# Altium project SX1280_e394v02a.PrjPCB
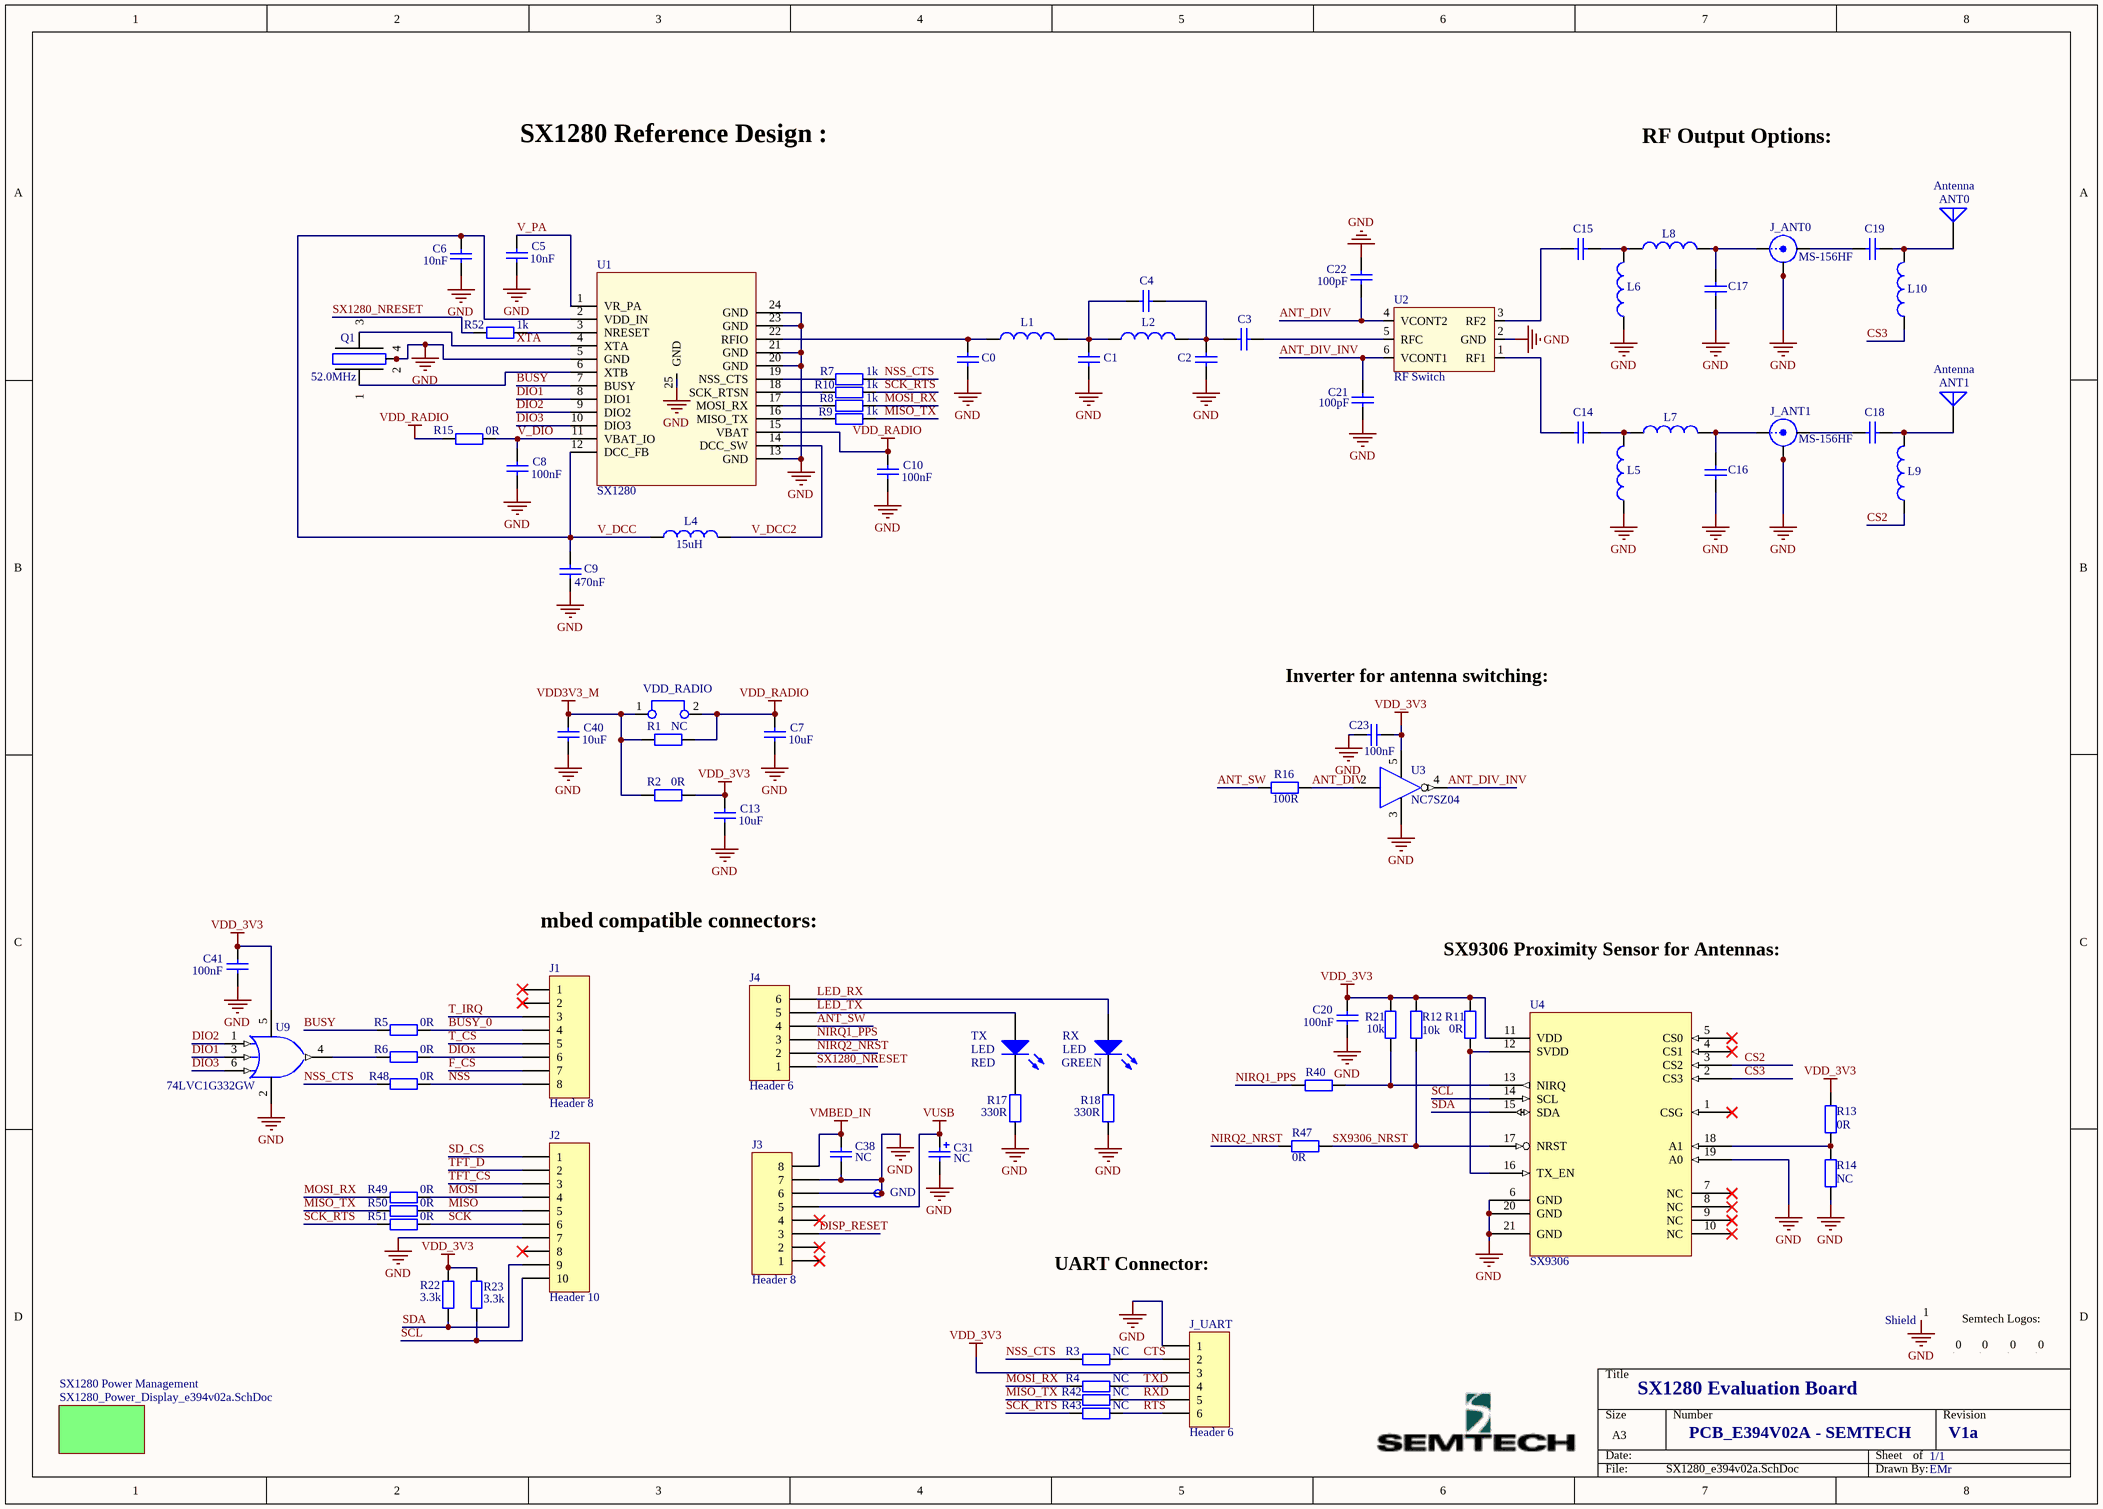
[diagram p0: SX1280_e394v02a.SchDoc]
2 sheets, 155 parts. Net scope: global (net labels, ports and power ports of the same name join across sheets).
Board file: SX1280_e394v02a.PcbDoc
Sheets:
  SX1280_e394v02a.SchDoc
    SX1280 Power Management = SX1280_Power_Display_e394v02a.SchDoc

## Sheet SX1280_e394v02a.SchDoc
size A3; DocumentNumber: 1; SheetNumber: 1; SheetTotal: 2; VersionControl_RevNumber: 1

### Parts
ANT0  Antenna  [ANT_2.4GHz_microstrip]
ANT1  Antenna  [ANT_2.4GHz_microstrip]
C0  Cap  [rlc_402_smd]  (value not drawn)
C1  Cap  [rlc_402_smd]  (value not drawn)
C2  Cap  [rlc_402_smd]  (value not drawn)
C3  Cap  [rlc_402_smd]  (value not drawn)
C4  Cap  [rlc_402_smd]  (value not drawn)
C5  value 10nF  [rlc_402_smd]  (hidden comment: Cap)
C6  value 10nF  [rlc_402_smd]  (hidden comment: Cap)
C7  value 10uF  [rlc_805_smd]  (hidden comment: Cap)
C8  value 100nF  [rlc_402_smd]  (hidden comment: Cap)
C9  value 470nF  [rlc_402_smd]  (hidden comment: Cap)
C10  value 100nF  [rlc_402_smd]  (hidden comment: Cap)
C13  value 10uF  [rlc_805_smd]  (hidden comment: Cap)
C14  Cap  [rlc_402_smd]  (value not drawn)
C15  Cap  [rlc_402_smd]  (value not drawn)
C16  Cap  [rlc_402_smd]  (value not drawn)
C17  Cap  [rlc_402_smd]  (value not drawn)
C18  Cap  [rlc_402_smd]  (value not drawn)
C19  Cap  [rlc_402_smd]  (value not drawn)
C20  value 100nF  [rlc_402_smd]  (hidden comment: Cap)
C21  value 100pF  [rlc_402_smd]  (hidden comment: Cap)
C22  value 100pF  [rlc_402_smd]  (hidden comment: Cap)
C23  value 100nF  [rlc_402_smd]  (hidden comment: Cap)
C31  value NC  [CD3216-1206]  (hidden comment: Cap Pol)
C38  value NC  [rlc_805_smd]  (hidden comment: Cap)
C40  value 10uF  [rlc_805_smd]  (hidden comment: Cap)
C41  value 100nF  [rlc_402_smd]  (hidden comment: Cap)
GND  Test Pin  [pin_0.9mm]  (value not drawn)
J1  Header 8  [HDR1X8]
J2  Header 10  [HDR1X10]
J3  Header 8  [HDR1X8]
J4  Header 6  [HDR1X6]
J_ANT0  MS-156HF  [MS-156HF Hirose]
J_ANT1  MS-156HF  [MS-156HF Hirose]
J_UART  Header 6  [HDR1X6]
L1  Inductor  [rlc_402_smd]  (value not drawn)
L2  Inductor  [rlc_402_smd]  (value not drawn)
L4  value 15uH  [rlc_805_smd enlarged]  (hidden comment: Inductor)
L5  Inductor  [rlc_402_smd]  (value not drawn)
L6  Inductor  [rlc_402_smd]  (value not drawn)
L7  Inductor  [rlc_402_smd]  (value not drawn)
L8  Inductor  [rlc_402_smd]  (value not drawn)
L9  Inductor  [rlc_402_smd]  (value not drawn)
L10  Inductor  [rlc_402_smd]  (value not drawn)
Logo_Bot  Logo symbol  [logo_semtech_horiz_size4]  (value not drawn)
Logo_ESD  Logo symbol  [Logo ESD]  (value not drawn)
Logo_Recycling1  Logo symbol  [Logo Recycling1]  (value not drawn)
Logo_Semtech_S  Logo symbol  [logo_semtech_horiz_size3]  (value not drawn)
Q1  value 52.0MHz  [nd2016da]  (hidden comment: Xtal)
R1  value NC  [rlc_603_smd]  (hidden comment: Resistor)
R2  value 0R  [rlc_603_smd]  (hidden comment: Resistor)
R3  value NC  [rlc_402_smd]  (hidden comment: Resistor)
R4  value NC  [rlc_402_smd]  (hidden comment: Resistor)
R5  value 0R  [rlc_402_smd]  (hidden comment: Resistor)
R6  value 0R  [rlc_402_smd]  (hidden comment: Resistor)
R7  value 1k  [rlc_201_smd]  (hidden comment: Resistor)
R8  value 1k  [rlc_201_smd]  (hidden comment: Resistor)
R9  value 1k  [rlc_201_smd]  (hidden comment: Resistor)
R10  value 1k  [rlc_201_smd]  (hidden comment: Resistor)
R11  value 0R  [rlc_402_smd]  (hidden comment: Resistor)
R12  value 10k  [rlc_402_smd]  (hidden comment: Resistor)
R13  value 0R  [rlc_402_smd]  (hidden comment: Resistor)
R14  value NC  [rlc_402_smd]  (hidden comment: Resistor)
R15  value 0R  [rlc_402_smd]  (hidden comment: Resistor)
R16  value 100R  [rlc_402_smd]  (hidden comment: Resistor)
R17  value 330R  [rlc_402_smd]  (hidden comment: Resistor)
R18  value 330R  [rlc_402_smd]  (hidden comment: Resistor)
R21  value 10k  [rlc_402_smd]  (hidden comment: Resistor)
R22  value 3.3k  [rlc_402_smd]  (hidden comment: Resistor)
R23  value 3.3k  [rlc_402_smd]  (hidden comment: Resistor)
R40  Resistor  [rlc_402_smd]  (value not drawn)
R42  value NC  [rlc_402_smd]  (hidden comment: Resistor)
R43  value NC  [rlc_402_smd]  (hidden comment: Resistor)
R47  value 0R  [rlc_402_smd]  (hidden comment: Resistor)
R48  value 0R  [rlc_402_smd]  (hidden comment: Resistor)
R49  value 0R  [rlc_402_smd]  (hidden comment: Resistor)
R50  value 0R  [rlc_402_smd]  (hidden comment: Resistor)
R51  value 0R  [rlc_402_smd]  (hidden comment: Resistor)
R52  value 1k  [rlc_201_smd]  (hidden comment: Resistor)
RX  LED  value GREEN  [LGM676 LED]
Shield  Logo symbol  [BMIS-209-F - Shield]  (value not drawn)
TX  LED  value RED  [LGM676 LED]
U1  SX1280  [vqfn24_4x4mm]
U2  RF Switch  [MiniMold-6]
U3  NC7SZ04  [SC70-5]
U4  SX9306  [vqfn20_3x3mm]
U9  74LVC1G332GW  [SOT363-6]
VDD_RADIO  Jumper  [bridge_254mm]  (value not drawn)

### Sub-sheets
SX1280 Power Management = SX1280_Power_Display_e394v02a.SchDoc: no entries

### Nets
GND: C0.2 C1.1 C2.1 C5.1 C6.1 C7.1 C8.1 C9.1 C10.1 C13.1 C16.2 C17.2 C20.2 C21.1 C22.1 C23.1 C31.2 C38.1 C40.1 C41.1 GND.1(pin) J2.7 J3.6 J3.7 J_ANT0.3(GND) J_ANT0.4(GND) J_ANT1.3(GND) J_ANT1.4(GND) J_UART.1 L5.1 L6.1 Q1.2 Q1.4 R14.1 R17.1 R18.1 Shield.1 U1.5(GND) U1.13(GND) U1.20(GND) U1.21(GND) U1.23(GND) U1.24(GND) U1.25(GND) U2.2(GND) U3.3(GND) U4.6(GND) U4.19(A0) U4.20(GND) U4.21(GND) U9.2(GND)
VDD3V3_M: C40.2 R1.2 R2.2 VDD_RADIO.1
VDD_3V3: C13.2 C20.1 C23.2 C41.2 J_UART.3 R2.1 R11.1 R12.2 R13.2 R21.2 R22.2 R23.2 U3.5(VCC) U4.11(VDD) U9.5(VCC)
VDD_RADIO: C7.2 C10.2 R1.1 R15.2 U1.15(VBAT) VDD_RADIO.2
VMBED_IN: C38.2 J3.8
VUSB: C31.1 J3.5
ANT_DIV: C22.2 R16.1 U2.4(VCONT2) U3.2(A)
ANT_DIV_INV: C21.2 U2.6(VCONT1) U3.4(Y)
ANT_SW: J4.4 R16.2
BUSY: R5.2 U1.7(BUSY)
BUSY_0: J1.4 R5.1
CS2: L9.1 U4.3(CS2)
CS3: L10.1 U4.2(CS3)
CTS: J_UART.2 R3.1
DIO1: U1.8(DIO1) U9.3(B)
DIO2: U1.9(DIO2) U9.1(A)
DIO3: U1.10(DIO3) U9.6(C)
DIOx: J1.6 R6.1
DISP_RESET: J3.3
F_CS: J1.7
LED_RX: J4.6 RX.1(A)
LED_TX: J4.5 TX.1(A)
MISO: J2.5 R50.1
MISO_TX: R9.1 R42.2 R50.2
MOSI: J2.4 R49.1
MOSI_RX: R4.2 R8.1 R49.2
NIRQ1_PPS: J4.3 R40.1
NIRQ2_NRST: J4.2 R47.1
NSS: J1.8 R48.1
NSS_CTS: R3.2 R7.1 R48.2
RTS: J_UART.6 R43.1
RXD: J_UART.5 R42.1
SCK: J2.6 R51.1
SCK_RTS: R10.1 R43.2 R51.2
SCL: J2.10 R23.1 U4.14(SCL)
SD_CS: J2.1
SDA: J2.9 R22.1 U4.15(SDA)
SX1280_NRESET: J4.1 R52.2
SX9306_NRST: R12.1 R47.2 U4.17(NRST)
T_CS: J1.5
T_IRQ: J1.3
TFT_CS: J2.3
TFT_D: J2.2
TXD: J_UART.4 R4.1
V_DCC: C6.2 C9.2 L4.1 U1.2(VDD_IN) U1.12(DCC_FB)
V_DCC2: L4.2 U1.14(DCC_SW)
V_DIO: C8.2 R15.1 U1.11(VBAT_IO)
V_PA: C5.2 U1.1(VR_PA)
XTA: Q1.3 U1.4(XTA)
NetANT0_1: ANT0.1(A) C19.1 L10.2
NetANT1_1: ANT1.1(A) C18.1 L9.2
NetC0_1: C0.1 L1.1 U1.22(RFIO)
NetC1_2: C1.2 C4.1 L1.2 L2.1
NetC2_2: C2.2 C3.1 C4.2 L2.2
NetC3_2: C3.2 U2.5(RFC)
NetC14_1: C14.1 L5.2 L7.1
NetC14_2: C14.2 U2.1(RF1)
NetC15_1: C15.1 L6.2 L8.1
NetC15_2: C15.2 U2.3(RF2)
NetC16_1: C16.1 J_ANT1.2(Signal) L7.2
NetC17_1: C17.1 J_ANT0.2(Signal) L8.2
NetC18_2: C18.2 J_ANT1.1(Signal)
NetC19_2: C19.2 J_ANT0.1(Signal)
NetQ1_1: Q1.1 U1.6(XTB)
NetR6_2: R6.2 U9.4(Y)
NetR7_2: R7.2 U1.19(NSS_CTS)
NetR8_2: R8.2 U1.17(MOSI_RX)
NetR9_2: R9.2 U1.16(MISO_TX)
NetR10_2: R10.2 U1.18(SCK_RTSN)
NetR11_2: R11.2 U4.12(SVDD) U4.16(TX_EN)
NetR13_1: R13.1 R14.2 U4.18(A1)
NetR17_2: R17.2 TX.2(K)
NetR18_2: R18.2 RX.2(K)
NetR21_1: R21.1 R40.2 U4.13(NIRQ)
NetR52_1: R52.1 U1.3(NRESET)

Not connected (* = marked no-connect by the designer): J1 1* 2*; J2 8*; J3 1* 2* 4*; Logo_Bot 0; Logo_ESD 0; Logo_Recycling1 0; Logo_Semtech_S 0; U4 1(CSG)* 4(CS1)* 5(CS0)* 7(NC)* 8(NC)* 9(NC)* 10(NC)*

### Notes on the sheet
- SX1280 Reference Design :
- RF Output Options:
- (near C23) Inverter for antenna switching:
- mbed compatible connectors:
- SX9306 Proximity Sensor for Antennas:
- UART Connector:
- Semtech Logos:
- SX1280 Evaluation Board
- PCB_E394V02A - SEMTECH
- 1/1
- V1a
- EMr

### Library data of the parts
ANT0 ANT1 = Antenna: Generic Antenna
C0-C4 C14-C19 = Cap: Capacitor SMD; Value: NC
C5-C10 C13 C20-C23 C38 C40 C41 = Cap: Capacitor SMD
C31 = Cap Pol: Polarized Capacitor (Surface Mount)
GND = test_pin
J1 J3 = Header 8: Header, 8-Pin
J2 = Header 10: Header, 10-Pin
J4 J_UART = Header 6: Header, 6-Pin
J_ANT0 J_ANT1 = MS-156HF: MS-156HF Hirose RF Connector
L1 L2 L5-L10 = Inductor: Inductor SMD; Code_IEC: 1005; Value: 0R
L4 = Inductor: Inductor SMD; Code_IEC: 1005
Logo_Bot Logo_ESD Logo_Recycling1 Logo_Semtech_S = Logo: Schematic symbol for Logo
Q1 = Xtal GND: Crystal with GND pins; 4 pins
R1-R18 R21-R23 R42 R43 R47-R52 = Resistor: Resistor SMD - IEC symbol version
R40 = Resistor: Resistor SMD - IEC symbol version; Value: NC
Shield = Shield: Shield - EMI Gasket - Standard Surface Mount Shields
U1 = SX1280: SX1280 - Ultra low power RF transceiver
U2 = CG2214M6 RF Switch
U3 = NC7SZ04: NC7SZ04 - TinyLogic HS Single Inverter - Fairchild Semi
U4 = SX9306: Ultra Low Power, Smart Proximity Sensor for SAR
U9 = 74LVC1G332GW: Triple 3-Input OR Gate, 6-Pin
VDD_RADIO = Jumper: Jumper Wire

## Sheet SX1280_Power_Display_e394v02a.SchDoc
size A3; DocumentNumber: 2; SheetNumber: 2; SheetTotal: 2
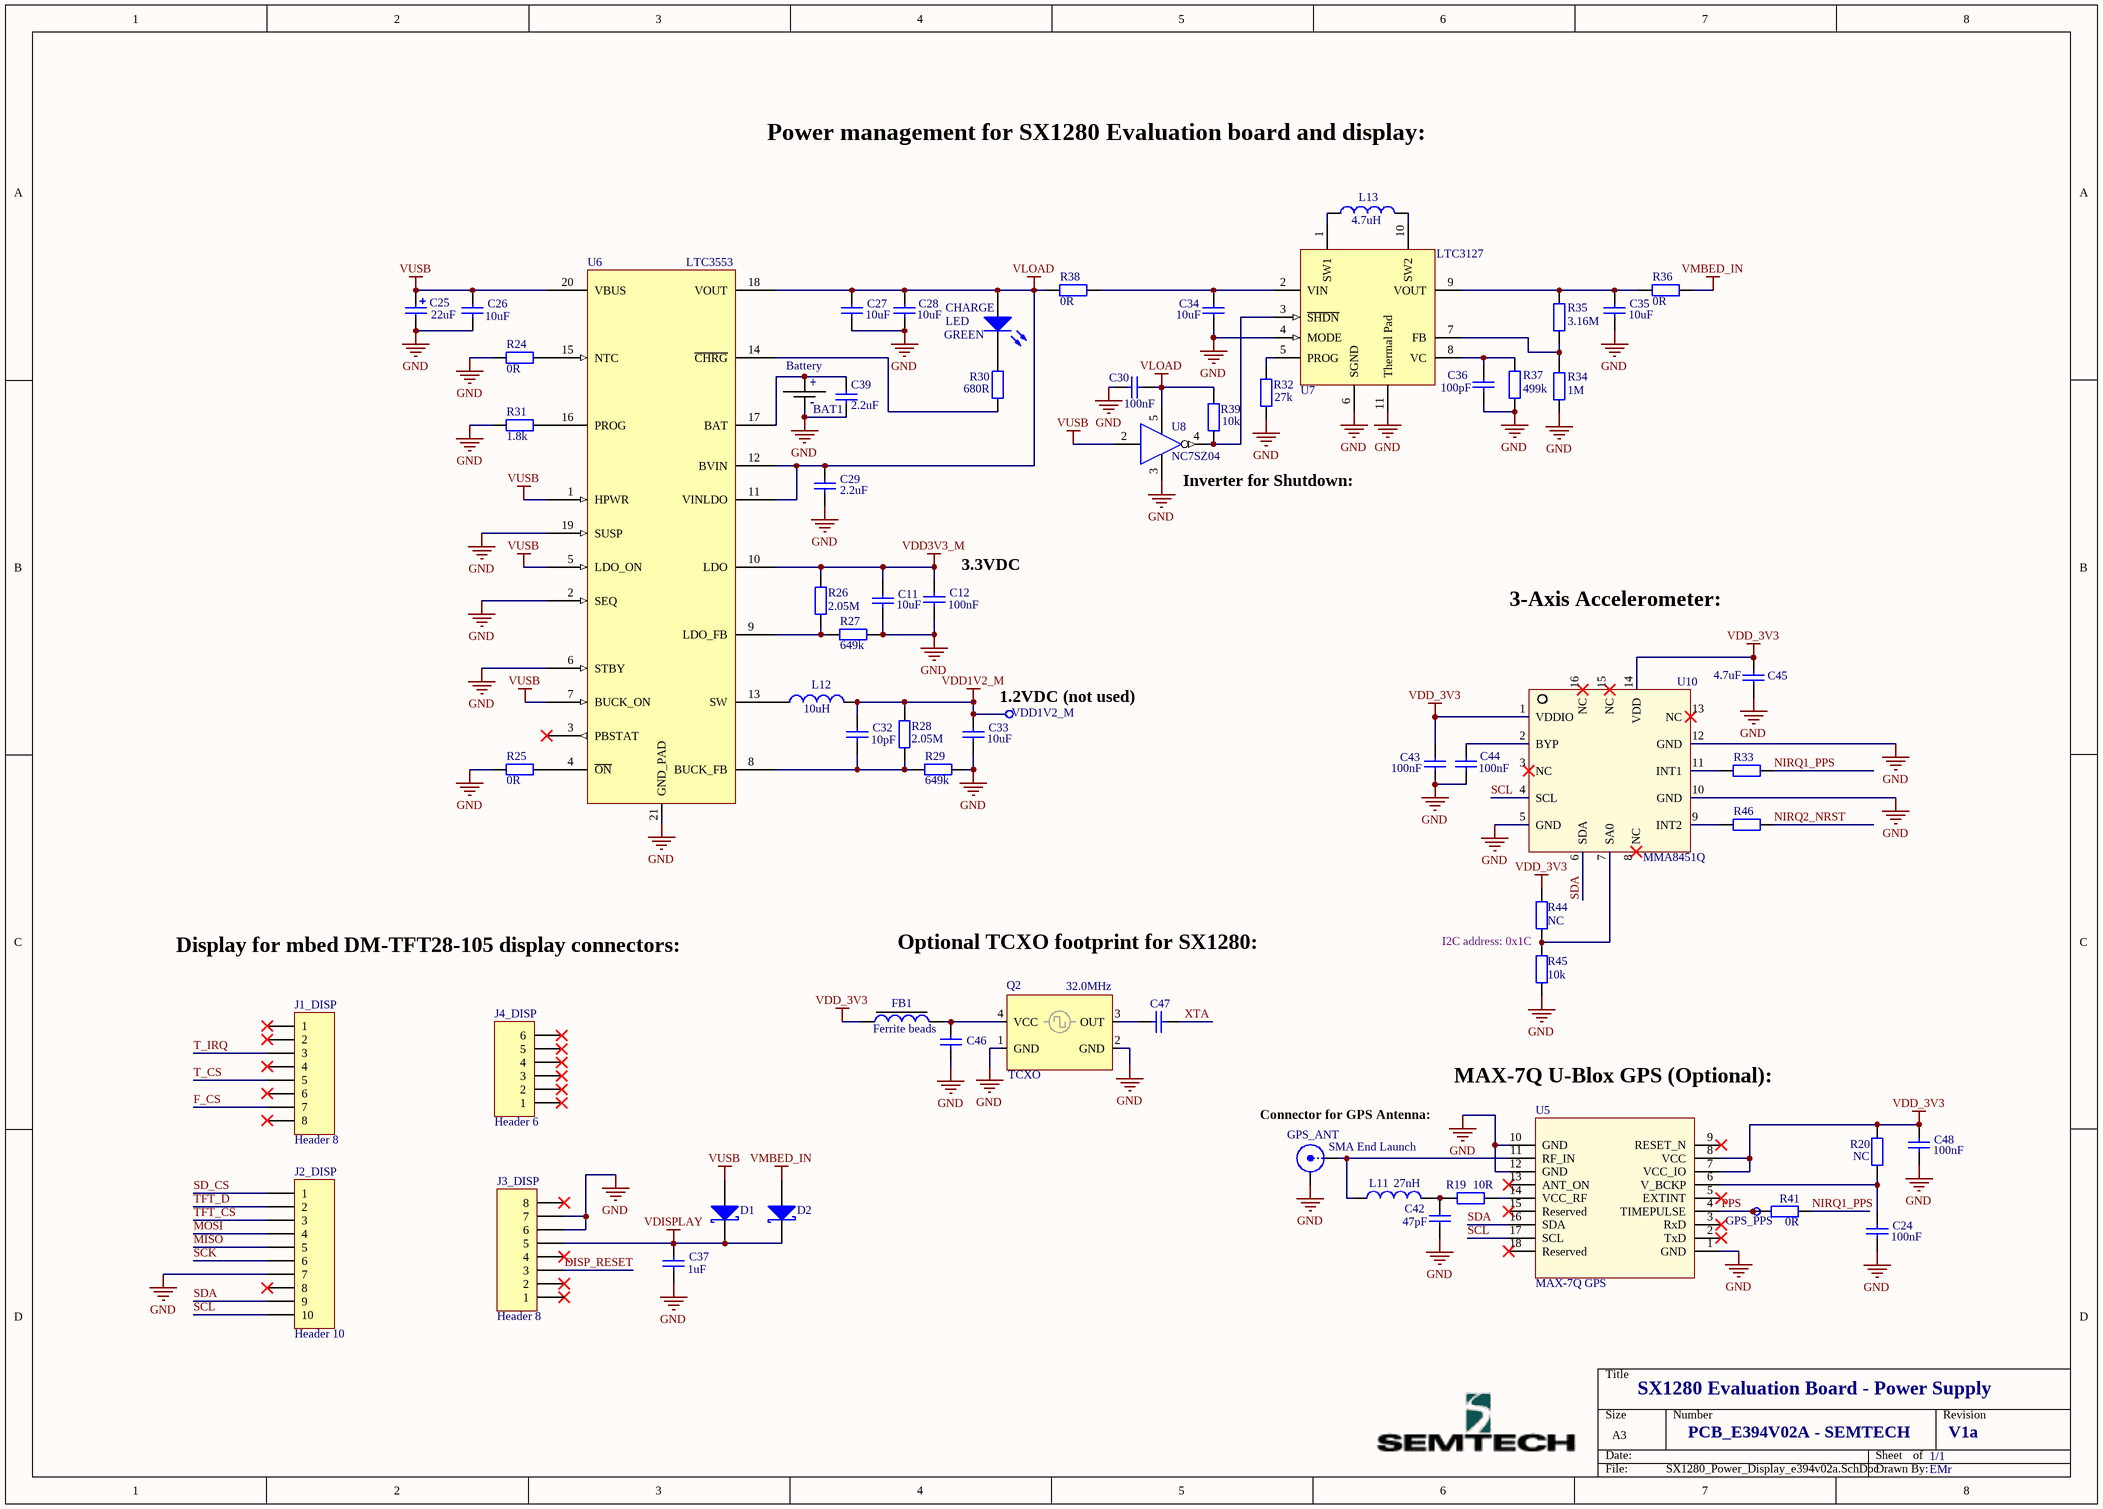
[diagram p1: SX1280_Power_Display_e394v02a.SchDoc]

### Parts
BAT1  Battery  [S2B-PH-K-S]
C11  value 10uF  [rlc_805_smd]  (hidden comment: Cap)
C12  value 100nF  [rlc_402_smd]  (hidden comment: Cap)
C24  value 100nF  [rlc_402_smd]  (hidden comment: Cap)
C25  value 22uF  [CD3216-1206]  (hidden comment: Cap Pol)
C26  value 10uF  [rlc_805_smd]  (hidden comment: Cap)
C27  value 10uF  [rlc_805_smd]  (hidden comment: Cap)
C28  value 10uF  [rlc_805_smd]  (hidden comment: Cap)
C29  value 2.2uF  [rlc_603_smd]  (hidden comment: Cap)
C30  value 100nF  [rlc_402_smd]  (hidden comment: Cap)
C32  value 10pF  [rlc_402_smd]  (hidden comment: Cap)
C33  value 10uF  [rlc_805_smd]  (hidden comment: Cap)
C34  value 10uF  [rlc_805_smd]  (hidden comment: Cap)
C35  value 10uF  [rlc_805_smd]  (hidden comment: Cap)
C36  value 100pF  [rlc_402_smd]  (hidden comment: Cap)
C37  value 1uF  [rlc_402_smd]  (hidden comment: Cap)
C39  value 2.2uF  [rlc_603_smd]  (hidden comment: Cap)
C42  value 47pF  [rlc_402_smd]  (hidden comment: Cap)
C43  value 100nF  [rlc_402_smd]  (hidden comment: Cap)
C44  value 100nF  [rlc_402_smd]  (hidden comment: Cap)
C45  value 4.7uF  [rlc_603_smd]  (hidden comment: Cap)
C46  Cap  [rlc_402_smd]  (value not drawn)
C47  Cap  [rlc_402_smd]  (value not drawn)
C48  value 100nF  [rlc_402_smd]  (hidden comment: Cap)
CHARGE  LED  value GREEN  [LGM676 LED]
D1  D Schottky single  [SOD123]  (value not drawn)
D2  D Schottky single  [SOD123]  (value not drawn)
FB1  Ferrite beads  [rlc_402_smd]
GPS_ANT  SMA End Launch  [SMA END LAUNCH JACK RECEPTACLE SHORT]
GPS_PPS  Test Pin  [pin_1mm]  (value not drawn)
J1_DISP  Header 8  [HDR1X8]
J2_DISP  Header 10  [HDR1X10]
J3_DISP  Header 8  [HDR1X8]
J4_DISP  Header 6  [HDR1X6]
L11  value 27nH  [rlc_402_smd]  (hidden comment: Inductor)
L12  value 10uH  [L4818]  (hidden comment: Inductor)
L13  value 4.7uH  [L4818]  (hidden comment: Inductor)
Q2  TCXO  value 32.0MHz  [TCXO 2.0x1.6mm]
R19  value 10R  [rlc_402_smd]  (hidden comment: Resistor)
R20  value NC  [rlc_402_smd]  (hidden comment: Resistor)
R24  value 0R  [rlc_402_smd]  (hidden comment: Resistor)
R25  value 0R  [rlc_402_smd]  (hidden comment: Resistor)
R26  value 2.05M  [rlc_402_smd]  (hidden comment: Resistor)
R27  value 649k  [rlc_402_smd]  (hidden comment: Resistor)
R28  value 2.05M  [rlc_402_smd]  (hidden comment: Resistor)
R29  value 649k  [rlc_402_smd]  (hidden comment: Resistor)
R30  value 680R  [rlc_402_smd]  (hidden comment: Resistor)
R31  value 1.8k  [rlc_402_smd]  (hidden comment: Resistor)
R32  value 27k  [rlc_402_smd]  (hidden comment: Resistor)
R33  Resistor  [rlc_402_smd]  (value not drawn)
R34  value 1M  [rlc_402_smd]  (hidden comment: Resistor)
R35  value 3.16M  [rlc_402_smd]  (hidden comment: Resistor)
R36  value 0R  [rlc_603_smd]  (hidden comment: Resistor)
R37  value 499k  [rlc_402_smd]  (hidden comment: Resistor)
R38  value 0R  [rlc_603_smd]  (hidden comment: Resistor)
R39  value 10k  [rlc_402_smd]  (hidden comment: Resistor)
R41  value 0R  [rlc_402_smd]  (hidden comment: Resistor)
R44  value NC  [rlc_402_smd]  (hidden comment: Resistor)
R45  value 10k  [rlc_402_smd]  (hidden comment: Resistor)
R46  Resistor  [rlc_402_smd]  (value not drawn)
U5  MAX-7Q GPS  [MAX-7]
U6  LTC3553  [vqfn20_3x3mm]
U7  LTC3127  [DD10_L]
U8  NC7SZ04  [SC70-5]
U10  MMA8451Q  [vqfn16_3x3mm]
VDD1V2_M  Test Pin  [pin_1mm]  (value not drawn)

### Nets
GND: BAT1.2(-) C11.1 C12.1 C24.2 C25.2 C26.1 C27.1 C28.1 C29.1 C30.1 C33.1 C34.1 C35.1 C36.1 C37.1 C39.1 C42.2 C43.1 C44.1 C45.1 C46.1 C48.2 GPS_ANT.2(GND) J2_DISP.7 J3_DISP.6 J3_DISP.7 Q2.1(GND) Q2.2(GND) R24.2 R25.2 R27.2 R29.2 R31.2 R32.2 R34.1 R37.1 R45.2 U5.1(GND) U5.10(GND) U5.12(GND) U6.2(SEQ) U6.6(STBY) U6.19(SUSP) U6.21(GND_PAD) U7.4(MODE) U7.6(SGND) U7.11(Thermal_Pad) U8.3(GND) U10.5(GND) U10.10(GND) U10.12(GND)
VDD1V2_M: C32.2 C33.2 L12.2 R28.1 VDD1V2_M.1(pin)
VDD3V3_M: C11.2 C12.2 R26.1 U6.10(LDO)
VDD_3V3: C43.2 C45.2 C48.1 FB1.1 R20.1 R44.1 U5.7(VCC_IO) U5.8(VCC) U10.1(VDDIO) U10.14(VDD)
VDISPLAY: C37.2 D1.2(K) D2.2(K) J3_DISP.5
VLOAD: C27.2 C28.2 C29.2 C30.2 CHARGE.1(A) R38.1 R39.1 U6.11(VINLDO) U6.12(BVIN) U6.18(VOUT) U8.5(VCC)
VMBED_IN: D2.1(A) R36.2
VUSB: C25.1 C26.2 D1.1(A) U6.1(HPWR) U6.5(LDO_ON) U6.7(BUCK_ON) U6.20(VBUS) U8.2(A)
DISP_RESET: J3_DISP.3
F_CS: J1_DISP.7
MISO: J2_DISP.5
MOSI: J2_DISP.4
NIRQ1_PPS: R33.2 R41.2
NIRQ2_NRST: R46.2
PPS: GPS_PPS.1(pin) R41.1 U5.4(TIMEPULSE)
SCK: J2_DISP.6
SCL: J2_DISP.10 U5.17(SCL) U10.4(SCL)
SD_CS: J2_DISP.1
SDA: J2_DISP.9 U5.16(SDA) U10.6(SDA)
T_CS: J1_DISP.5
T_IRQ: J1_DISP.3
TFT_CS: J2_DISP.3
TFT_D: J2_DISP.2
XTA: C47.2
NetBAT1_1: BAT1.1(+) C39.2 U6.17(BAT)
NetC24_1: C24.1 R20.2 U5.6(V_BCKP)
NetC32_1: C32.1 R28.2 R29.1 U6.8(BUCK_FB)
NetC34_2: C34.2 R38.2 U7.2(VIN)
NetC35_2: C35.2 R35.2 R36.1 U7.9(VOUT)
NetC36_2: C36.2 R37.2 U7.8(VC)
NetC42_1: C42.1 L11.2 R19.2
NetC44_2: C44.2 U10.2(BYP)
NetC46_2: C46.2 FB1.2 Q2.4(VCC)
NetC47_1: C47.1 Q2.3(OUT)
NetCHARGE_2: CHARGE.2(K) R30.2
NetGPS_ANT_1: GPS_ANT.1(Signal) L11.1 U5.11(RF_IN)
NetL12_1: L12.1 U6.13(SW)
NetL13_1: L13.1 U7.1(SW1)
NetL13_2: L13.2 U7.10(SW2)
NetR19_1: R19.1 U5.14(VCC_RF)
NetR24_1: R24.1 U6.15(NTC)
NetR25_1: R25.1 U6.4(~{ON})
NetR26_2: R26.2 R27.1 U6.9(LDO_FB)
NetR30_1: R30.1 U6.14(~{CHRG})
NetR31_1: R31.1 U6.16(PROG)
NetR32_1: R32.1 U7.5(PROG)
NetR33_1: R33.1 U10.11(INT1)
NetR34_2: R34.2 R35.1 U7.7(FB)
NetR39_2: R39.2 U7.3(~{SHDN}) U8.4(Y)
NetR44_2: R44.2 R45.1 U10.7(SA0)
NetR46_1: R46.1 U10.9(INT2)

Not connected (* = marked no-connect by the designer): J1_DISP 1* 2* 4* 6* 8*; J2_DISP 8*; J3_DISP 1* 2* 4* 8*; J4_DISP 1* 2* 3* 4* 5* 6*; U5 2(TxD)* 3(RxD)* 5(EXTINT)* 9(RESET_N)* 13(ANT_ON)* 15(Reserved)* 18(Reserved)*; U6 3(PBSTAT)*; U10 3(NC)* 8(NC)* 13(NC)* 15(NC)* 16(NC)*

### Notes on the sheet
- Power management for SX1280 Evaluation board and display:
- (near U8) Inverter for Shutdown:
- (near C12) 3.3VDC
- 3-Axis Accelerometer:
- (near VDD1V2_M) 1.2VDC (not used)
- Display for mbed DM-TFT28-105 display connectors:
- Optional TCXO footprint for SX1280:
- I2C address: 0x1C
- (near GPS_ANT) Connector for GPS Antenna:
- MAX-7Q U-Blox GPS (Optional):
- SX1280 Evaluation Board - Power Supply
- PCB_E394V02A - SEMTECH
- 1/1
- V1a
- EMr

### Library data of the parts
BAT1 = Battery: Baterry standard modif
C11 C12 C24 C26-C30 C32-C37 C39 C42-C44 C48 = Cap: Capacitor SMD
C25 = Cap Pol: Polarized Capacitor (Surface Mount)
C45 = Cap: Capacitor SMD; Value voltage: 16VDC
C46 = Cap: Capacitor SMD; Value: 100nF
C47 = Cap: Capacitor SMD; Value: 15pF
D1 D2 = D Schottky single: Schottky Diode
FB1 = Ferrite beads: Value: NC
GPS_ANT = SMA: SMA Straight Connector
GPS_PPS VDD1V2_M = test_pin
J1_DISP J3_DISP = Header 8: Header, 8-Pin
J2_DISP = Header 10: Header, 10-Pin
J4_DISP = Header 6: Header, 6-Pin
L11 = Inductor: Inductor SMD; Code_IEC: 1005
L12 L13 = Inductor: Code_IEC: 1005
R19 R20 R24-R32 R34-R39 R41 R44 R45 = Resistor: Resistor SMD - IEC symbol version
R33 R46 = Resistor: as R40 on sheet SX1280_e394v02a
U5 = MAX-7Q: MAX-7Q; U-Blox; 7 GPS/GNSS modules
U6 = LTC3553: Micropower USB Power Manager With Li-Ion Charger,  LDO and Buck Regulator
U7 = LTC3127: LTC3127EDD#PBF - 1A Buck-Boost DC/DC  Converter with Programmable  Input Current Limit
U8 = NC7SZ04: as U3 on sheet SX1280_e394v02a
U10 = MMA8451Q: Xtrinsic MMA8451Q 3-Axis, 14-bit/8-bit Digital Accelerometer

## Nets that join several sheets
GND: SX1280_e394v02a (51 pins), SX1280_Power_Display_e394v02a (51 pins)
VDD3V3_M: SX1280_e394v02a (C40.2 R1.2 R2.2 VDD_RADIO.1), SX1280_Power_Display_e394v02a (C11.2 C12.2 R26.1 U6.10)
VDD_3V3: SX1280_e394v02a (15 pins), SX1280_Power_Display_e394v02a (10 pins)
VMBED_IN: SX1280_e394v02a (C38.2 J3.8), SX1280_Power_Display_e394v02a (D2.1 R36.2)
VUSB: SX1280_e394v02a (C31.1 J3.5), SX1280_Power_Display_e394v02a (8 pins)
DISP_RESET: SX1280_e394v02a (J3.3), SX1280_Power_Display_e394v02a (J3_DISP.3)
F_CS: SX1280_e394v02a (J1.7), SX1280_Power_Display_e394v02a (J1_DISP.7)
MISO: SX1280_e394v02a (J2.5 R50.1), SX1280_Power_Display_e394v02a (J2_DISP.5)
MOSI: SX1280_e394v02a (J2.4 R49.1), SX1280_Power_Display_e394v02a (J2_DISP.4)
NIRQ1_PPS: SX1280_e394v02a (J4.3 R40.1), SX1280_Power_Display_e394v02a (R33.2 R41.2)
NIRQ2_NRST: SX1280_e394v02a (J4.2 R47.1), SX1280_Power_Display_e394v02a (R46.2)
SCK: SX1280_e394v02a (J2.6 R51.1), SX1280_Power_Display_e394v02a (J2_DISP.6)
SCL: SX1280_e394v02a (J2.10 R23.1 U4.14), SX1280_Power_Display_e394v02a (J2_DISP.10 U5.17 U10.4)
SD_CS: SX1280_e394v02a (J2.1), SX1280_Power_Display_e394v02a (J2_DISP.1)
SDA: SX1280_e394v02a (J2.9 R22.1 U4.15), SX1280_Power_Display_e394v02a (J2_DISP.9 U5.16 U10.6)
T_CS: SX1280_e394v02a (J1.5), SX1280_Power_Display_e394v02a (J1_DISP.5)
T_IRQ: SX1280_e394v02a (J1.3), SX1280_Power_Display_e394v02a (J1_DISP.3)
TFT_CS: SX1280_e394v02a (J2.3), SX1280_Power_Display_e394v02a (J2_DISP.3)
TFT_D: SX1280_e394v02a (J2.2), SX1280_Power_Display_e394v02a (J2_DISP.2)
XTA: SX1280_e394v02a (Q1.3 U1.4), SX1280_Power_Display_e394v02a (C47.2)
